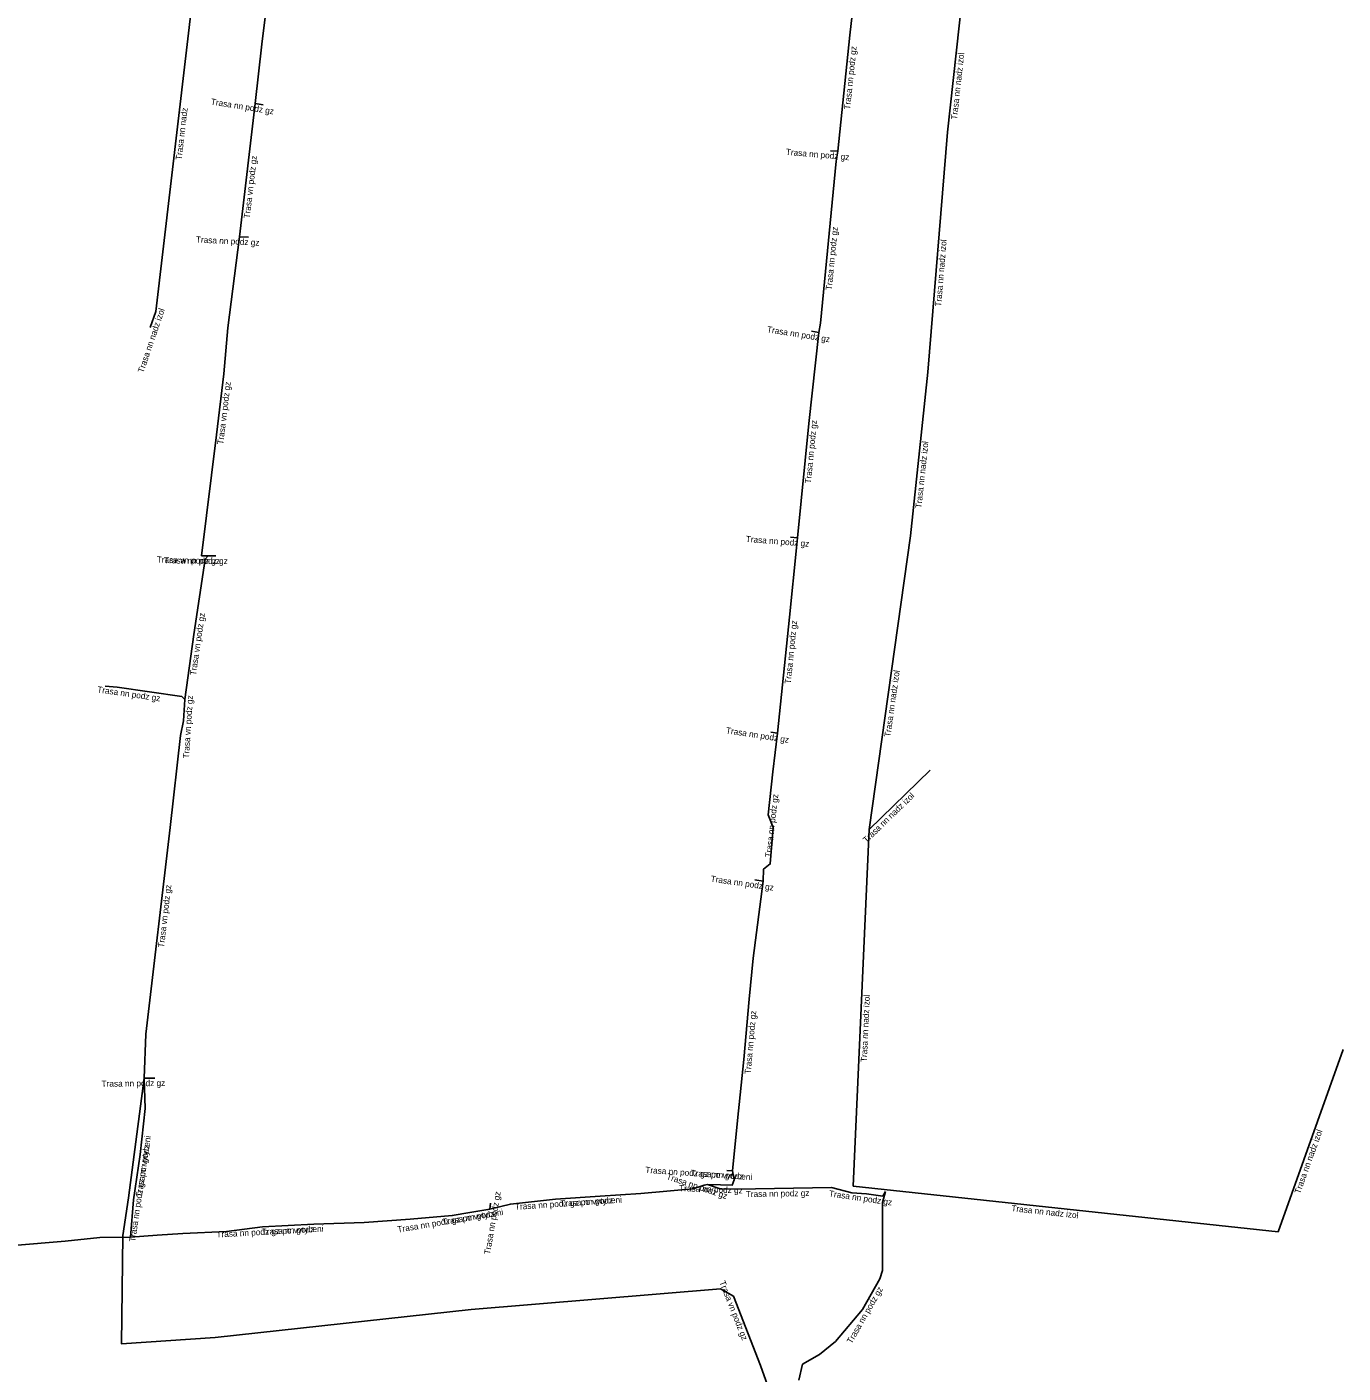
# Model space of a CAD drawing. Extents: x -772942 to -772530, y -1033745 to -1033298.
# Drawn here: x -772765.4 to -772658.6, y -1033602.6 to -1033493.3 of the extents above; entities that cross this region are included whole.
import ezdxf

# ---------------------------------------------------------------- set-up
doc = ezdxf.new("R2010")
doc.units = 0
for name, color, linetype in [('Popiskový text - Ostatní atributy Trasy', 7, 'Continuous'), ('Spojnice NN', 7, 'Continuous'), ('Spojnice VN', 7, 'Continuous')]:
    doc.layers.add(name, color=color, linetype=linetype)

msp = doc.modelspace()

# ---------------------------------------------------------------- linework, layer by layer
at = {"layer": 'Spojnice NN'}
for points in [[(-772754.97, -1033516.4), (-772751.34, -1033485.48)], [(-772699.63, -1033503.41), (-772698.66, -1033493.99), (-772698.06, -1033488.79)], [(-772690.72, -1033501.87), (-772689.54, -1033490.98)], [(-772746.92, -1033499.53), (-772746.25, -1033499.63)], [(-772692.33, -1033521.33), (-772690.72, -1033501.87)], [(-772701.16, -1033518.12), (-772701.03, -1033517.36), (-772699.75, -1033504.2), (-772699.63, -1033503.41)], [(-772699.63, -1033503.41), (-772700.22, -1033503.36)], [(-772748.18, -1033510.34), (-772747.44, -1033510.38)], [(-772755.42, -1033517.72), (-772754.97, -1033516.4)], [(-772702.89, -1033534.79), (-772701.98, -1033525.51), (-772701.16, -1033518.12)], [(-772701.16, -1033518.12), (-772701.75, -1033518.02)], [(-772693.73, -1033534.61), (-772692.33, -1033521.33)], [(-772704.51, -1033550.63), (-772703.54, -1033541.22), (-772702.97, -1033535.59), (-772702.89, -1033534.79)], [(-772702.89, -1033534.79), (-772703.46, -1033534.74)], [(-772697.07, -1033558.46), (-772693.73, -1033534.61)], [(-772750.72, -1033536.24), (-772750.09, -1033536.25)], [(-772752.62, -1033547.91), (-772752.85, -1033547.66), (-772758.1, -1033546.9), (-772759.09, -1033546.81)], [(-772705.69, -1033562.64), (-772705.65, -1033561.66), (-772705.11, -1033561.25), (-772704.86, -1033558.28), (-772705.29, -1033557.25), (-772704.89, -1033553.77), (-772704.51, -1033550.63)], [(-772704.51, -1033550.63), (-772705.05, -1033550.55)], [(-772697.07, -1033558.46), (-772692.13, -1033553.65)], [(-772698.37, -1033587.39), (-772697.07, -1033558.46)], [(-772705.69, -1033562.64), (-772706.49, -1033568.89), (-772706.81, -1033572.22), (-772707.25, -1033577.13), (-772707.76, -1033582.08), (-772708.18, -1033586.15)], [(-772705.69, -1033562.64), (-772706.36, -1033562.54)], [(-772663.88, -1033591.11), (-772658.62, -1033576.3)], [(-772757.02, -1033591.53), (-772756.79, -1033588.51), (-772756.24, -1033584.82), (-772755.84, -1033581.11), (-772755.92, -1033578.64)], [(-772757.02, -1033591.53), (-772756.79, -1033588.51), (-772756.24, -1033584.82), (-772755.84, -1033581.11), (-772755.92, -1033578.64)], [(-772755.92, -1033578.64), (-772755.06, -1033578.63)], [(-772710.19, -1033587.27), (-772709.14, -1033587.28), (-772708.2, -1033587.31), (-772708.03, -1033586.9), (-772708.18, -1033586.15)], [(-772708.18, -1033586.15), (-772708.62, -1033586.12)], [(-772708.18, -1033586.15), (-772708.62, -1033586.12)], [(-772710.19, -1033587.27), (-772710.48, -1033587.33), (-772711.4, -1033587.63), (-772715.61, -1033588), (-772718.9, -1033588.2), (-772722.53, -1033588.45), (-772726.2, -1033588.86), (-772727.88, -1033589.26)], [(-772710.19, -1033587.27), (-772710.48, -1033587.33), (-772711.4, -1033587.63), (-772715.61, -1033588), (-772718.9, -1033588.2), (-772722.53, -1033588.45), (-772726.2, -1033588.86), (-772727.88, -1033589.26)], [(-772709.18, -1033587.61), (-772710.19, -1033587.27)], [(-772697.29, -1033588.02), (-772698.49, -1033587.94), (-772700.14, -1033587.52), (-772707.85, -1033587.65), (-772709.18, -1033587.61)], [(-772695.75, -1033587.84), (-772696.01, -1033588.72), (-772696, -1033594.24), (-772696.22, -1033594.93), (-772697.63, -1033597.4), (-772699.81, -1033600), (-772701.1, -1033601.07), (-772702.48, -1033601.85), (-772702.79, -1033603.16)], [(-772698.37, -1033587.39), (-772663.88, -1033591.11)], [(-772695.75, -1033587.84), (-772695.98, -1033588.21), (-772697.29, -1033588.02)], [(-772727.88, -1033589.26), (-772729.49, -1033589.53)], [(-772727.88, -1033589.26), (-772729.49, -1033589.53)], [(-772727.8, -1033588.79), (-772727.88, -1033589.26)], [(-772729.49, -1033589.53), (-772730.92, -1033589.79), (-772734.34, -1033590.09), (-772738.06, -1033590.34), (-772742.16, -1033590.48), (-772746.32, -1033590.71), (-772749.24, -1033591.09), (-772752.77, -1033591.23), (-772754.86, -1033591.38), (-772757.02, -1033591.53)], [(-772729.49, -1033589.53), (-772730.92, -1033589.79), (-772734.34, -1033590.09), (-772738.06, -1033590.34), (-772742.16, -1033590.48), (-772746.32, -1033590.71), (-772749.24, -1033591.09), (-772752.77, -1033591.23), (-772754.86, -1033591.38), (-772757.02, -1033591.53)], [(-772757.02, -1033591.53), (-772759.52, -1033591.58), (-772762.34, -1033591.87), (-772766.52, -1033592.22), (-772768.82, -1033592.59), (-772772.83, -1033593.04), (-772777.4, -1033593.21), (-772780.24, -1033593.38), (-772783.53, -1033593.47), (-772786.92, -1033593.96), (-772790.83, -1033594.3), (-772792.34, -1033594.42), (-772794.22, -1033594.33), (-772797.84, -1033593.77), (-772801.37, -1033593.47), (-772804.09, -1033593.21)], [(-772757.02, -1033591.53), (-772759.52, -1033591.58), (-772762.34, -1033591.87), (-772766.52, -1033592.22), (-772768.82, -1033592.59), (-772772.83, -1033593.04), (-772777.4, -1033593.21), (-772780.24, -1033593.38), (-772783.53, -1033593.47), (-772786.92, -1033593.96), (-772790.83, -1033594.3), (-772792.34, -1033594.42), (-772794.22, -1033594.33), (-772797.84, -1033593.77), (-772801.37, -1033593.47), (-772804.09, -1033593.21)]]:
    msp.add_lwpolyline(points, dxfattribs=at)
at = {"layer": 'Spojnice VN'}
for points in [[(-772743.16, -1033469.59), (-772745.23, -1033485.51), (-772746.38, -1033494.71), (-772746.92, -1033499.53)], [(-772746.92, -1033499.53), (-772748.18, -1033510.34)], [(-772748.18, -1033510.34), (-772749.13, -1033517.75), (-772749.46, -1033521.46), (-772750.06, -1033526.41), (-772751.27, -1033536.23)], [(-772752.62, -1033547.91), (-772751.88, -1033542.62), (-772750.98, -1033536.5), (-772750.72, -1033536.24)], [(-772750.72, -1033536.24), (-772751.27, -1033536.23)], [(-772752.73, -1033549.63), (-772752.62, -1033547.91)], [(-772752.73, -1033549.63), (-772752.96, -1033550.82), (-772753.81, -1033558.28), (-772755.79, -1033575.06), (-772755.92, -1033578.64)], [(-772755.92, -1033578.64), (-772757.18, -1033588.36), (-772757.66, -1033591.41), (-772757.77, -1033600.19), (-772750.15, -1033599.68), (-772729.38, -1033597.41), (-772709.15, -1033595.74), (-772708.1, -1033596.33), (-772705.9, -1033601.95), (-772703.84, -1033607.73), (-772703.63, -1033609.74), (-772703.68, -1033610.68), (-772706.5, -1033632.96), (-772709.03, -1033655.17), (-772710.84, -1033670.81), (-772710.63, -1033671.61)]]:
    msp.add_lwpolyline(points, dxfattribs=at)

# ---------------------------------------------------------------- texts
at = {"layer": 'Popiskový text - Ostatní atributy Trasy'}
for s, rotation, p in [('Trasa nn podz gz', 84.1208, (-772698.63, -1033500.04)), ('Trasa nn nadz izol', 83.8498, (-772689.95, -1033500.86)), ('Trasa nn nadz', 83.2956, (-772752.88, -1033504.14)), ('Trasa nn podz gz', 351.0098, (-772750.53, -1033499.61)), ('Trasa vn podz gz', 83.3599, (-772747.35, -1033508.88)), ('Trasa nn podz gz', 355.0053, (-772703.86, -1033503.69)), ('Trasa nn podz gz', 84.4446, (-772700.12, -1033514.7)), ('Trasa nn podz gz', 357.0722, (-772751.73, -1033510.81)), ('Trasa nn nadz izol', 85.2673, (-772691.24, -1033516.03)), ('Trasa nn nadz izol', 71.4146, (-772755.98, -1033521.43)), ('Trasa nn podz gz', 350.7737, (-772705.4, -1033518.09)), ('Trasa vn podz gz', 83.1321, (-772749.5, -1033527.23)), ('Trasa nn podz gz', 84.3995, (-772701.81, -1033530.39)), ('Trasa nn nadz izol', 83.9688, (-772692.84, -1033532.4)), ('Trasa nn podz gz', 355.5173, (-772707.11, -1033535.11)), ('Trasa vn podz gz', 358.6558, (-772754.9, -1033536.79)), ('Trasa nn podz gz', 359.2748, (-772754.3, -1033536.85)), ('Trasa vn podz gz', 81.6341, (-772751.72, -1033545.97)), ('Trasa nn podz gz', 84.1146, (-772703.45, -1033546.65)), ('Trasa nn nadz izol', 82.0327, (-772695.36, -1033550.97)), ('Trasa nn podz gz', 351.763, (-772759.75, -1033547.32)), ('Trasa vn podz gz', 86.3407, (-772752.28, -1033552.7)), ('Trasa nn podz gz', 351.2222, (-772708.73, -1033550.64)), ('Trasa nn podz gz', 83.4431, (-772705.04, -1033560.74)), ('Trasa nn nadz izol', 44.2398, (-772697.29, -1033559.58)), ('Trasa vn podz gz', 83.265, (-772754.31, -1033568.06)), ('Trasa nn podz gz', 351.7984, (-772709.97, -1033562.68)), ('Trasa nn nadz izol', 87.4252, (-772697.27, -1033577.34)), ('Trasa nn podz gz', 84.8792, (-772706.7, -1033578.32)), ('Trasa nn podz gz', 0.8004, (-772759.37, -1033579.34)), ('Trasa nn nadz izol', 70.4696, (-772662.11, -1033588.06)), ('Trasa nn podz gz po vytyceni', 81.5224, (-772756.65, -1033591.95)), ('Trasa nn podz', 81.5224, (-772756.1, -1033588.31)), ('Trasa nn podz gz po vytyceni', 356.0995, (-772715.26, -1033586.32)), ('Trasa nn podz', 356.0995, (-772711.58, -1033586.57)), ('Trasa nn podz gz', 341.4628, (-772713.58, -1033586.82)), ('Trasa nn podz gz', 357.8268, (-772712.51, -1033587.8)), ('Trasa nn podz gz', 80.3401, (-772727.85, -1033592.97)), ('Trasa nn podz gz po vytyceni', 3.9398, (-772725.81, -1033589.33)), ('Trasa nn podz', 3.9398, (-772722.13, -1033589.07)), ('Trasa nn podz gz', 0.966, (-772707.09, -1033588.29)), ('Trasa nn podz gz', 351.7475, (-772700.37, -1033588.23)), ('Trasa nn podz gz po vytyceni', 9.52, (-772735.32, -1033591.17)), ('Trasa nn podz', 9.52, (-772731.68, -1033590.56)), ('Trasa nn nadz izol', 353.8409, (-772685.56, -1033589.43)), ('Trasa nn podz gz po vytyceni', 3.1646, (-772750.04, -1033591.57)), ('Trasa nn podz', 3.1646, (-772746.36, -1033591.36)), ('Trasa vn podz gz', 291.4414, (-772709.25, -1033595.19)), ('Trasa nn podz gz', 60.2801, (-772698.5, -1033600.23))]:
    msp.add_text(s, height=0.5, rotation=rotation, dxfattribs=at).set_placement(p)

doc.saveas('drawing.dxf')
